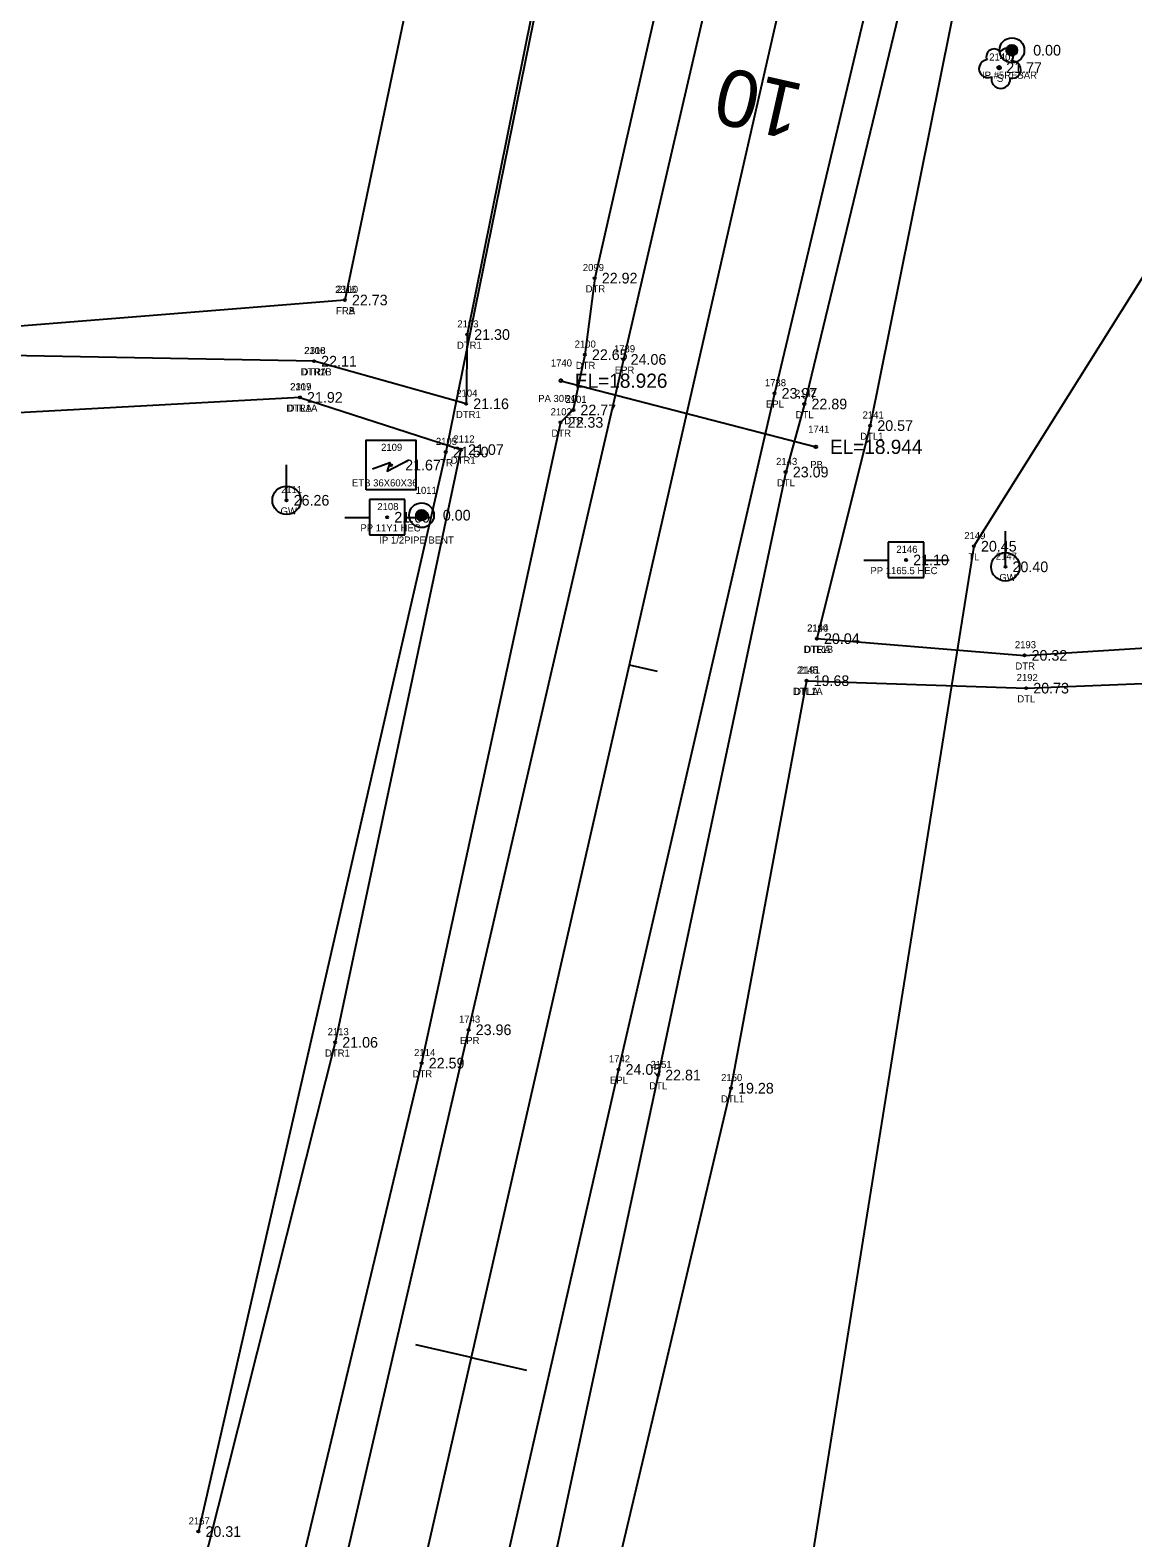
# Model space of a CAD drawing. Extents: x 2654414 to 2656963, y 761776 to 764965.
# Drawn here: x 2655349 to 2655504.2, y 761884 to 762096.2 of the extents above; entities that cross this region are included whole.
import ezdxf

# ---------------------------------------------------------------- set-up
doc = ezdxf.new("R2010")
doc.units = 0
for name, color, linetype in [('Default', 7, 'Continuous'), ('RD_EX_DR_Pipe', 7, 'Continuous'), ('RD_EX_DR_Pipe_txCode', 7, 'Continuous'), ('RD_EX_DV_Prop_txCode', 7, 'Continuous'), ('RD_EX_DV_PropPin', 7, 'Continuous'), ('RD_EX_Fence_Other', 7, 'Continuous'), ('RD_EX_Fence_Other_txCode', 7, 'Continuous'), ('RD_EX_H2O', 7, 'Continuous'), ('RD_EX_H2O_txCode', 7, 'Continuous'), ('RD_EX_Road', 7, 'Continuous'), ('RD_EX_Road_txCode', 7, 'Continuous'), ('RD_EX_TX_DV_Prop_ELEV', 7, 'Continuous'), ('RD_EX_TX_Fence_Other_ELEV', 7, 'Continuous'), ('RD_EX_TX_H2O_ELEV', 7, 'Continuous'), ('RD_EX_TX_Road_ELEV', 7, 'Continuous'), ('RD_EX_TX_UT_ELEV', 7, 'Continuous'), ('RD_EX_TX_VEG_ELEV', 7, 'Continuous'), ('RD_EX_UT', 7, 'Continuous'), ('RD_EX_UT_txCode', 7, 'Continuous'), ('RD_EX_VEG', 7, 'Continuous'), ('RD_EX_VEG_txCode', 7, 'Continuous'), ('RD_HC_Cl', 7, 'Continuous'), ('RD_HC_Data_Tic', 7, 'Continuous'), ('RD_HC_Survey_ELEV', 7, 'Continuous'), ('RD_HC_TX_Sta50', 7, 'Continuous'), ('RD_SMD_Locator', 7, 'Continuous'), ('RD_TX_Pipe_ElevEX', 7, 'Continuous')]:
    doc.layers.add(name, color=color, linetype=linetype)

msp = doc.modelspace()

# ---------------------------------------------------------------- linework, layer by layer
at = {"layer": 'Default'}
msp.add_line((2656050.51, 764712.37), (2655383.26, 761787.51), dxfattribs=at)
at = {"layer": 'RD_EX_DR_Pipe'}
msp.add_line((2655423.66, 762046.88), (2655459.55, 762037.57), dxfattribs=at)
at = {"layer": 'RD_EX_DV_PropPin'}
for p, q in [((2655486.41, 762093.2), (2655486.41, 762093.59)), ((2655486.45, 762093.1), (2655486.45, 762093.69)), ((2655486.48, 762093.03), (2655486.48, 762093.77)), ((2655486.52, 762092.97), (2655486.52, 762093.82)), ((2655486.55, 762092.92), (2655486.55, 762093.87)), ((2655486.59, 762092.88), (2655486.59, 762093.91)), ((2655486.62, 762092.84), (2655486.62, 762093.95)), ((2655486.66, 762092.81), (2655486.66, 762093.98)), ((2655486.69, 762092.79), (2655486.69, 762094.01)), ((2655486.73, 762092.76), (2655486.73, 762094.03)), ((2655486.76, 762092.74), (2655486.76, 762094.05)), ((2655486.8, 762092.72), (2655486.8, 762094.07)), ((2655486.83, 762092.7), (2655486.83, 762094.09)), ((2655486.87, 762092.69), (2655486.87, 762094.1)), ((2655486.9, 762092.68), (2655486.9, 762094.12)), ((2655486.94, 762092.66), (2655486.94, 762094.13)), ((2655486.97, 762092.65), (2655486.97, 762094.14)), ((2655487.01, 762092.65), (2655487.01, 762094.14)), ((2655487.04, 762092.64), (2655487.04, 762094.15)), ((2655487.08, 762092.64), (2655487.08, 762094.15)), ((2655487.11, 762092.64), (2655487.11, 762094.16)), ((2655487.15, 762092.63), (2655487.15, 762094.16)), ((2655487.18, 762092.64), (2655487.18, 762094.16)), ((2655487.22, 762092.64), (2655487.22, 762094.15)), ((2655487.25, 762092.64), (2655487.25, 762094.15)), ((2655487.29, 762092.65), (2655487.29, 762094.14)), ((2655487.32, 762092.65), (2655487.32, 762094.14)), ((2655487.36, 762092.66), (2655487.36, 762094.13)), ((2655487.39, 762092.68), (2655487.39, 762094.12)), ((2655487.43, 762092.69), (2655487.43, 762094.1)), ((2655487.46, 762092.7), (2655487.46, 762094.09)), ((2655487.5, 762092.72), (2655487.5, 762094.07)), ((2655487.53, 762092.74), (2655487.53, 762094.05)), ((2655487.57, 762092.76), (2655487.57, 762094.03)), ((2655487.6, 762092.79), (2655487.6, 762094.01)), ((2655487.64, 762092.81), (2655487.64, 762093.98)), ((2655487.67, 762092.84), (2655487.67, 762093.95)), ((2655487.71, 762092.88), (2655487.71, 762093.91)), ((2655487.74, 762092.92), (2655487.74, 762093.87)), ((2655487.78, 762092.97), (2655487.78, 762093.82)), ((2655487.81, 762093.03), (2655487.81, 762093.77)), ((2655487.85, 762093.1), (2655487.85, 762093.69)), ((2655487.88, 762093.2), (2655487.88, 762093.59)), ((2655403.34, 762027.75), (2655403.34, 762028.15)), ((2655403.37, 762027.65), (2655403.37, 762028.25)), ((2655403.41, 762027.58), (2655403.41, 762028.32)), ((2655403.44, 762027.52), (2655403.44, 762028.38)), ((2655403.48, 762027.47), (2655403.48, 762028.42)), ((2655403.51, 762027.43), (2655403.51, 762028.46)), ((2655403.55, 762027.4), (2655403.55, 762028.5)), ((2655403.58, 762027.37), (2655403.58, 762028.53)), ((2655403.62, 762027.34), (2655403.62, 762028.56)), ((2655403.65, 762027.31), (2655403.65, 762028.58)), ((2655403.69, 762027.29), (2655403.69, 762028.61)), ((2655403.72, 762027.27), (2655403.72, 762028.62)), ((2655403.76, 762027.26), (2655403.76, 762028.64)), ((2655403.79, 762027.24), (2655403.79, 762028.66)), ((2655403.83, 762027.23), (2655403.83, 762028.67)), ((2655403.86, 762027.22), (2655403.86, 762028.68)), ((2655403.9, 762027.21), (2655403.9, 762028.69)), ((2655403.93, 762027.2), (2655403.93, 762028.7)), ((2655403.97, 762027.2), (2655403.97, 762028.7)), ((2655404, 762027.19), (2655404, 762028.71)), ((2655404.04, 762027.19), (2655404.04, 762028.71)), ((2655404.07, 762027.19), (2655404.07, 762028.71)), ((2655404.11, 762027.19), (2655404.11, 762028.71)), ((2655404.14, 762027.19), (2655404.14, 762028.71)), ((2655404.18, 762027.2), (2655404.18, 762028.7)), ((2655404.21, 762027.2), (2655404.21, 762028.7)), ((2655404.25, 762027.21), (2655404.25, 762028.69)), ((2655404.28, 762027.22), (2655404.28, 762028.68)), ((2655404.32, 762027.23), (2655404.32, 762028.67)), ((2655404.35, 762027.24), (2655404.35, 762028.66)), ((2655404.39, 762027.26), (2655404.39, 762028.64)), ((2655404.42, 762027.27), (2655404.42, 762028.62)), ((2655404.46, 762027.29), (2655404.46, 762028.61)), ((2655404.49, 762027.31), (2655404.49, 762028.58)), ((2655404.53, 762027.34), (2655404.53, 762028.56)), ((2655404.56, 762027.37), (2655404.56, 762028.53)), ((2655404.6, 762027.4), (2655404.6, 762028.5)), ((2655404.63, 762027.43), (2655404.63, 762028.46)), ((2655404.67, 762027.47), (2655404.67, 762028.42)), ((2655404.7, 762027.52), (2655404.7, 762028.38)), ((2655404.74, 762027.58), (2655404.74, 762028.32)), ((2655404.77, 762027.65), (2655404.77, 762028.25)), ((2655404.81, 762027.75), (2655404.81, 762028.15))]:
    msp.add_line(p, q, dxfattribs=at)
for centre, radius in [((2655487.15, 762093.4), 1.75), ((2655487.15, 762093.4), 0.761), ((2655404.07, 762027.95), 1.75), ((2655404.07, 762027.95), 0.761)]:
    msp.add_circle(centre, radius, dxfattribs=at)
at = {"layer": 'RD_EX_Fence_Other'}
msp.add_lwpolyline([(2655431.78, 762175.86), (2655417.3, 762172.91), (2655393.28, 762058.24), (2655393.28, 762058.24), (2655337.57, 762053.75), (2655251.71, 762069.62), (2655221.44, 762090.34)], dxfattribs=at)
at = {"layer": 'RD_EX_H2O'}
for points in [[(2655458.25, 762004.65), (2655489.16, 762003.6), (2655538.42, 762005.59), (2655556.05, 762013.17), (2655587.88, 762051.39), (2655643.4, 762074.04), (2655655.85, 762091.76), (2655681.86, 762140.14), (2655683.72, 762146.53), (2655664.39, 762201.23), (2655621.98, 762271.36), (2655558.86, 762321.08)], [(2655459.71, 762010.57), (2655488.92, 762008.22), (2655537.08, 762011.25), (2655554.9, 762018.55), (2655583.72, 762054.68), (2655639.44, 762078.76), (2655651.66, 762094.07), (2655673.82, 762140.27), (2655676.22, 762150.22), (2655658.16, 762196.88), (2655618.83, 762267.48), (2655556.47, 762317.07), (2655558.86, 762321.08)], [(2655450.32, 762170.31), (2655445.39, 762174.97), (2655437.79, 762176.61), (2655429.86, 762149.53), (2655410.49, 762053.38), (2655410.35, 762043.63), (2655388.95, 762049.63)], [(2655450.32, 762170.31), (2655447.51, 762145.05), (2655428.44, 762061.32), (2655427.05, 762050.54), (2655425.43, 762042.76), (2655423.63, 762041.01), (2655404.09, 761950.81), (2655382.1, 761859.05), (2655367.49, 761795.82)], [(2655476.07, 762118.66), (2655457.95, 762043.6), (2655455.32, 762034.02), (2655437.36, 761949.13), (2655416.41, 761851.26), (2655413.59, 761836.57), (2655406.69, 761818.38), (2655416.71, 761813.93)], [(2655476.07, 762118.66), (2655482.7, 762117.53), (2655467.21, 762040.56), (2655459.71, 762010.57)], [(2655388.95, 762049.63), (2655313, 762051.05), (2655289.65, 762056.26), (2655236.79, 762050.02), (2655233.87, 762053.67)], [(2655386.96, 762044.53), (2655311.1, 762040.37), (2655293.44, 762044.27), (2655237.39, 762043.26), (2655233.87, 762053.67)], [(2655386.96, 762044.53), (2655409.62, 762037.18), (2655391.92, 761953.74), (2655368.61, 761861.23), (2655351.84, 761799.36)], [(2655458.25, 762004.65), (2655447.62, 761947.28), (2655424.45, 761849.54), (2655416.71, 761813.93)]]:
    msp.add_lwpolyline(points, dxfattribs=at)
at = {"layer": 'RD_EX_Road'}
for points in [[(2655700.99, 763232.28), (2655693.55, 763198.57), (2655671.65, 763102.04), (2655649.04, 763001.06), (2655627.27, 762906.23), (2655605, 762809.37), (2655598.99, 762783.09), (2655583.65, 762714.14), (2655561.97, 762618.32), (2655556.36, 762593.84), (2655548.11, 762557.14), (2655540.1, 762522.48), (2655518.03, 762425.04), (2655496.48, 762329.56), (2655475.55, 762236.62), (2655473.2, 762226.14), (2655466.57, 762197.5), (2655460.06, 762168.16), (2655454.26, 762143.78), (2655432.5, 762049.88), (2655410.7, 761955.51), (2655388.17, 761858.43), (2655373.5, 761793.95)], [(2655670.04, 762995.18), (2655648.57, 762900.67), (2655631.27, 762824.03), (2655626.67, 762802.87), (2655621.78, 762781.91), (2655611.71, 762738.43), (2655604.93, 762708.62), (2655582.64, 762610.54), (2655576.46, 762583.32), (2655561.41, 762517.24), (2655539.15, 762414.81), (2655531.98, 762386.15), (2655517.98, 762324.29), (2655508.17, 762280.15), (2655501.46, 762251.6), (2655496.92, 762232.09), (2655477.2, 762144.97), (2655472.14, 762122.52), (2655453.74, 762045.1), (2655431.79, 761949.92), (2655409.76, 761853.25), (2655401.25, 761816.42), (2655394.61, 761787.37)]]:
    msp.add_lwpolyline(points, dxfattribs=at)
at = {"layer": 'RD_EX_UT'}
for p, q in [((2655385.08, 762030.05), (2655385.08, 762035.05)), ((2655401.73, 762030.17), (2655396.73, 762030.17)), ((2655396.73, 762030.17), (2655396.73, 762025.17)), ((2655401.73, 762025.17), (2655401.73, 762030.17)), ((2655393.3, 762027.61), (2655396.76, 762027.61)), ((2655401.65, 762027.61), (2655405.3, 762027.61)), ((2655486.24, 762020.68), (2655486.24, 762025.68)), ((2655396.73, 762025.17), (2655401.73, 762025.17)), ((2655474.75, 762024.16), (2655469.75, 762024.16)), ((2655469.75, 762024.16), (2655469.75, 762019.16)), ((2655474.75, 762019.16), (2655474.75, 762024.16)), ((2655466.32, 762021.6), (2655469.79, 762021.6)), ((2655474.68, 762021.6), (2655478.32, 762021.6)), ((2655469.75, 762019.16), (2655474.75, 762019.16))]:
    msp.add_line(p, q, dxfattribs=at)
msp.add_lwpolyline([(2655396.27, 762031.5), (2655396.27, 762038.5), (2655403.27, 762038.5), (2655403.27, 762031.5)], close=True, dxfattribs=at)
msp.add_lwpolyline([(2655397.17, 762034.49), (2655399.59, 762035.39), (2655399.24, 762034.15), (2655402.29, 762035.74)], dxfattribs=at)
for centre in [(2655385.08, 762030.05), (2655486.24, 762020.68)]:
    msp.add_circle(centre, 2, dxfattribs=at)
at = {"layer": 'RD_EX_VEG'}
for points in [[(2655435.66, 762175.38), (2655407.48, 762036.84), (2655372.67, 761884.87)], [(2655560.2, 762061.65), (2655512.87, 762073.11), (2655481.8, 762023.58), (2655450.43, 761827.3), (2655477.86, 761831.84)]]:
    msp.add_lwpolyline(points, dxfattribs=at)
msp.add_circle((2655485.35, 762090.95), 0.25, dxfattribs=at)
for centre, radius, start, end in [((2655484.63, 762092.5), 1.08, 34.9763, 204.756), ((2655486.39, 762092.65), 0.995, 308.7626, 152.0467), ((2655483.78, 762090.8), 1.26, 96.4518, 294.734), ((2655487.19, 762090.67), 1.22, 256.5667, 98.1046), ((2655485.59, 762089.35), 1.32, 166.8827, 5.7589)]:
    msp.add_arc(centre, radius, start, end, dxfattribs=at)
at = {"layer": 'RD_HC_Cl'}
msp.add_line((2656050.51, 764712.37), (2655383.26, 761787.51), dxfattribs=at)
at = {"layer": 'RD_HC_Data_Tic'}
for p, q in [((2655433.31, 762006.88), (2655437.21, 762005.99)), ((2655411.07, 761909.38), (2655403.27, 761911.16)), ((2655411.07, 761909.38), (2655418.86, 761907.6))]:
    msp.add_line(p, q, dxfattribs=at)
at = {"layer": 'RD_SMD_Locator'}
for centre, radius in [((2655487.15, 762093.4), 0.15), ((2655485.35, 762090.95), 0.15), ((2655428.44, 762061.32), 0.15), ((2655393.28, 762058.24), 0.15), ((2655393.28, 762058.24), 0.15), ((2655410.49, 762053.38), 0.15), ((2655388.95, 762049.63), 0.15), ((2655388.95, 762049.63), 0.15), ((2655427.05, 762050.54), 0.15), ((2655432.5, 762049.88), 0.15), ((2655423.66, 762046.88), 0.2), ((2655386.96, 762044.53), 0.15), ((2655386.96, 762044.53), 0.15), ((2655453.74, 762045.1), 0.15), ((2655410.35, 762043.63), 0.15), ((2655425.43, 762042.76), 0.15), ((2655457.95, 762043.6), 0.15), ((2655423.63, 762041.01), 0.15), ((2655467.21, 762040.56), 0.15), ((2655407.48, 762036.84), 0.15), ((2655409.62, 762037.18), 0.15), ((2655459.55, 762037.57), 0.2), ((2655399.77, 762035), 0.15), ((2655455.32, 762034.02), 0.15), ((2655385.08, 762030.05), 0.15), ((2655399.24, 762027.66), 0.15), ((2655404.07, 762027.95), 0.15), ((2655481.8, 762023.58), 0.15), ((2655472.26, 762021.65), 0.15), ((2655486.24, 762020.68), 0.15), ((2655459.71, 762010.57), 0.15), ((2655459.71, 762010.57), 0.15), ((2655488.92, 762008.22), 0.15), ((2655458.25, 762004.65), 0.15), ((2655458.25, 762004.65), 0.15), ((2655489.16, 762003.6), 0.15), ((2655410.7, 761955.51), 0.15), ((2655391.92, 761953.74), 0.15), ((2655404.09, 761950.81), 0.15), ((2655431.79, 761949.92), 0.15), ((2655437.36, 761949.13), 0.15), ((2655447.62, 761947.28), 0.15), ((2655372.67, 761884.87), 0.15)]:
    msp.add_circle(centre, radius, dxfattribs=at)

# ---------------------------------------------------------------- texts
at = {"layer": 'RD_EX_DR_Pipe_txCode'}
for s, p in [('1740', (2655422.27, 762048.88)), ('PA 30RC', (2655420.49, 762043.88)), ('1741', (2655458.49, 762039.57)), ('PB', (2655458.77, 762034.57))]:
    msp.add_text(s, height=1, dxfattribs=at).set_placement(p)
at = {"layer": 'RD_EX_DV_Prop_txCode'}
for s, p in [('IP #5REBAR', (2655482.95, 762089.4)), ('1011', (2655403.25, 762030.95)), ('IP 1/2PIPE BENT', (2655398.13, 762023.95))]:
    msp.add_text(s, height=1, dxfattribs=at).set_placement(p)
at = {"layer": 'RD_EX_Fence_Other_txCode'}
for s, p in [('2316', (2655391.91, 762059.24)), ('2110', (2655392.17, 762059.24)), ('FRA', (2655392.03, 762056.24)), ('FRB', (2655392.05, 762056.24))]:
    msp.add_text(s, height=1, dxfattribs=at).set_placement(p)
at = {"layer": 'RD_EX_H2O_txCode'}
for s, p in [('2099', (2655426.77, 762062.32)), ('DTR', (2655427.17, 762059.32)), ('2103', (2655409.11, 762054.38)), ('2106', (2655387.54, 762050.63)), ('2318', (2655387.6, 762050.63)), ('DTR1', (2655409.06, 762051.38)), ('2100', (2655425.62, 762051.54)), ('DTR', (2655425.78, 762048.54)), ('DTR1B', (2655387.04, 762047.63)), ('DTRA', (2655387.19, 762047.63)), ('2107', (2655385.57, 762045.53)), ('2319', (2655385.61, 762045.53)), ('2104', (2655408.96, 762044.63)), ('2101', (2655424.33, 762043.76)), ('2142', (2655456.61, 762044.6)), ('DTR1A', (2655385.04, 762042.53)), ('DTLA', (2655385.23, 762042.53)), ('DTR1', (2655408.92, 762041.63)), ('2102', (2655422.24, 762042.01)), ('DTL', (2655456.71, 762041.6)), ('2141', (2655466.14, 762041.56)), ('DTR', (2655424.16, 762040.76)), ('2112', (2655408.56, 762038.18)), ('DTR', (2655422.36, 762039.01)), ('DTL1', (2655465.8, 762038.56)), ('DTR1', (2655408.19, 762035.18)), ('2143', (2655453.97, 762035.02)), ('DTL', (2655454.08, 762032.02)), ('2190', (2655458.32, 762011.57)), ('2144', (2655458.36, 762011.57)), ('DTL1B', (2655457.83, 762008.57)), ('DTRA', (2655457.95, 762008.57)), ('2193', (2655487.57, 762009.22)), ('2145', (2655456.9, 762005.65)), ('2191', (2655457.18, 762005.65)), ('DTR', (2655487.65, 762006.22)), ('2192', (2655487.82, 762004.6)), ('DTL1A', (2655456.35, 762002.65)), ('DTLA', (2655456.51, 762002.65)), ('DTL', (2655487.92, 762001.6)), ('2113', (2655390.86, 761954.74)), ('DTR1', (2655390.49, 761951.74)), ('2114', (2655403.03, 761951.81)), ('DTR', (2655402.82, 761948.81)), ('2151', (2655436.3, 761950.13)), ('2150', (2655446.23, 761948.28)), ('DTL', (2655436.11, 761947.13)), ('DTL1', (2655446.21, 761945.28))]:
    msp.add_text(s, height=1, dxfattribs=at).set_placement(p)
at = {"layer": 'RD_EX_Road_txCode'}
for s, p in [('1739', (2655431.15, 762050.88)), ('EPR', (2655431.27, 762047.88)), ('1738', (2655452.39, 762046.1)), ('EPL', (2655452.54, 762043.1)), ('1743', (2655409.35, 761956.51)), ('EPR', (2655409.47, 761953.51)), ('1742', (2655430.44, 761950.92)), ('EPL', (2655430.59, 761947.92))]:
    msp.add_text(s, height=1, dxfattribs=at).set_placement(p)
at = {"layer": 'RD_EX_TX_DV_Prop_ELEV'}
for p in [(2655490.15, 762092.65), (2655407.07, 762027.2)]:
    msp.add_text('0.00', height=1.5, dxfattribs=at).set_placement(p)
at = {"layer": 'RD_EX_TX_Fence_Other_ELEV'}
msp.add_text('22.73', height=1.5, dxfattribs=at).set_placement((2655394.28, 762057.49))
msp.add_text('22.73', height=1.5, dxfattribs=at).set_placement((2655394.28, 762057.49))
at = {"layer": 'RD_EX_TX_H2O_ELEV'}
for s, p in [('22.92', (2655429.44, 762060.57)), ('21.30', (2655411.49, 762052.63)), ('22.65', (2655428.05, 762049.79)), ('22.11', (2655389.95, 762048.88)), ('22.11', (2655389.95, 762048.88)), ('21.92', (2655387.96, 762043.78)), ('21.92', (2655387.96, 762043.78)), ('21.16', (2655411.35, 762042.88)), ('22.77', (2655426.43, 762042.01)), ('22.89', (2655458.95, 762042.85)), ('22.33', (2655424.63, 762040.26)), ('20.57', (2655468.21, 762039.81)), ('21.07', (2655410.62, 762036.43)), ('23.09', (2655456.32, 762033.27)), ('20.04', (2655460.71, 762009.82)), ('20.04', (2655460.71, 762009.82)), ('20.32', (2655489.92, 762007.47)), ('19.68', (2655459.25, 762003.9)), ('19.68', (2655459.25, 762003.9)), ('20.73', (2655490.16, 762002.85)), ('21.06', (2655392.92, 761952.99)), ('22.59', (2655405.09, 761950.06)), ('22.81', (2655438.36, 761948.38)), ('19.28', (2655448.62, 761946.53))]:
    msp.add_text(s, height=1.5, dxfattribs=at).set_placement(p)
at = {"layer": 'RD_EX_TX_Road_ELEV'}
for s, p in [('24.06', (2655433.5, 762049.13)), ('23.97', (2655454.74, 762044.35)), ('23.96', (2655411.7, 761954.76)), ('24.05', (2655432.79, 761949.17))]:
    msp.add_text(s, height=1.5, dxfattribs=at).set_placement(p)
at = {"layer": 'RD_EX_TX_UT_ELEV'}
for s, p in [('21.67', (2655401.77, 762034.25)), ('26.26', (2655386.08, 762029.3)), ('20.40', (2655487.24, 762019.93))]:
    msp.add_text(s, height=1.5, dxfattribs=at).set_placement(p)
at = {"layer": 'RD_EX_TX_VEG_ELEV'}
for s, p in [('21.77', (2655486.35, 762090.2)), ('21.50', (2655408.48, 762036.09)), ('20.45', (2655482.8, 762022.83)), ('20.31', (2655373.67, 761884.12))]:
    msp.add_text(s, height=1.5, dxfattribs=at).set_placement(p)
at = {"layer": 'RD_EX_UT_txCode'}
for s, p in [('2109', (2655398.38, 762037)), ('2111', (2655384.3, 762031.05)), ('ETB 36X60X36', (2655394.29, 762032)), ('GW', (2655384.23, 762028.05)), ('2108', (2655397.85, 762028.66)), ('PP 11Y1 HEC', (2655395.47, 762025.66)), ('2146', (2655470.89, 762022.65)), ('2147', (2655484.89, 762021.68)), ('PP 1165.5 HEC', (2655467.24, 762019.65)), ('GW', (2655485.39, 762018.68))]:
    msp.add_text(s, height=1, dxfattribs=at).set_placement(p)
at = {"layer": 'RD_EX_VEG_txCode'}
for s, p in [('2140', (2655483.96, 762091.95)), ('S', (2655485.04, 762088.95)), ('2105', (2655406.09, 762037.84)), ('TR', (2655406.68, 762034.84)), ('2149', (2655480.45, 762024.58)), ('TL', (2655481.02, 762021.58)), ('2167', (2655371.3, 761885.87))]:
    msp.add_text(s, height=1, dxfattribs=at).set_placement(p)
at = {"layer": 'RD_HC_Survey_ELEV'}
for s, p in [('21.69', (2655400.24, 762026.91)), ('21.10', (2655473.26, 762020.9))]:
    msp.add_text(s, height=1.5, dxfattribs=at).set_placement(p)
at = {"layer": 'RD_HC_TX_Sta50'}
msp.add_text('10', height=8, rotation=167.283, dxfattribs=at).set_placement((2655458.13, 762088.51))
at = {"layer": 'RD_TX_Pipe_ElevEX'}
for s, p in [('EL=18.926', (2655425.66, 762045.88)), ('EL=18.944', (2655461.55, 762036.57))]:
    msp.add_text(s, height=2, dxfattribs=at).set_placement(p)

doc.saveas('drawing.dxf')
